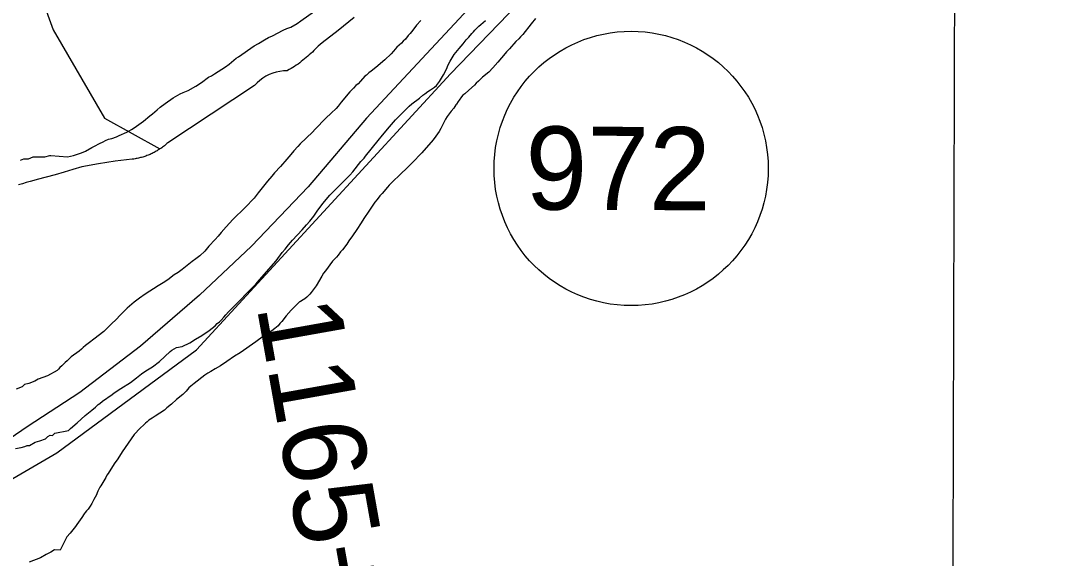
# Model space of a CAD drawing. Extents: x 3161514 to 3199414, y 831166 to 856601.
# Drawn here: x 3185519 to 3186751, y 838752 to 839399 of the extents above; entities that cross this region are included whole.
import ezdxf

# ---------------------------------------------------------------- set-up
doc = ezdxf.new("R2010")
doc.units = 0
for name, color, linetype in [('V-GRID-MAJR', 7, 'Continuous'), ('V-ROAD-CNTR', 7, 'Continuous'), ('V-ROAD-IDEN', 7, 'Continuous'), ('V-SITE-VEGE', 7, 'Continuous'), ('V-SURV-IDEN', 7, 'Continuous'), ('V-TOPO-SHOR', 7, 'Continuous')]:
    doc.layers.add(name, color=color, linetype=linetype)

msp = doc.modelspace()

# ---------------------------------------------------------------- linework, layer by layer
at = {"layer": 'V-GRID-MAJR'}
msp.add_spline([(3186635.6, 836575), (3186651.5, 842634.3), (3186667.4, 848696.7), (3186683.2, 854759.2), (3186683.2, 854762.2)], degree=3, dxfattribs=at)
at = {"layer": 'V-ROAD-CNTR'}
msp.add_lwpolyline([(3188785.6, 842348.3), (3188285.6, 841807.5), (3187778.5, 841264.8), (3187264.2, 840712), (3186692.9, 840089.5), (3186208.3, 839574.1), (3185935.3, 839281.4), (3185865.1, 839198.5), (3185797.1, 839127.5), (3185734.6, 839068.5), (3185663.3, 839007.1), (3185590.6, 838951.3), (3185527.2, 838910.2), (3185471.6, 838872.2), (3185410.6, 838843.5), (3185089.4, 838709.2), (3185045.4, 838695.8)], dxfattribs=at)
at = {"layer": 'V-ROAD-IDEN'}
msp.add_circle((3186253.9, 839220.8), 165, dxfattribs=at)
at = {"layer": 'V-SITE-VEGE'}
for p, q in [((3186065.7, 839387.2), (3186070.6, 839391.9)), ((3186070.6, 839391.9), (3186073.1, 839394.1)), ((3186073.1, 839394.1), (3186078.8, 839398.8)), ((3186133.7, 839394.7), (3186123.7, 839381.9)), ((3186138.8, 839401.1), (3186133.7, 839394.7)), ((3186055.5, 839375.5), (3186058.6, 839378.8)), ((3186058.6, 839378.8), (3186062.3, 839383.3)), ((3186062.3, 839383.3), (3186064.3, 839385.2)), ((3186064.3, 839385.2), (3186065.7, 839387.2)), ((3186120.9, 839379.2), (3186118.6, 839376.7)), ((3186123.7, 839381.9), (3186120.9, 839379.2)), ((3186040.9, 839357.7), (3186046.9, 839365.2)), ((3186046.9, 839365.2), (3186049.2, 839368)), ((3186049.2, 839368), (3186051.8, 839370.8)), ((3186051.8, 839370.8), (3186055.5, 839375.5)), ((3186107.5, 839364.7), (3186104.1, 839361.1)), ((3186115.2, 839373.3), (3186107.5, 839364.7)), ((3186118.6, 839376.7), (3186115.2, 839373.3)), ((3186036.1, 839349.9), (3186040.9, 839357.7)), ((3186097.8, 839353.9), (3186093.6, 839348.7)), ((3186100.4, 839356.7), (3186097.8, 839353.9)), ((3186104.1, 839361.1), (3186100.4, 839356.7)), ((3186028, 839333.5), (3186032, 839341)), ((3186032, 839341), (3186032.9, 839343.3)), ((3186032.9, 839343.3), (3186034.6, 839347.2)), ((3186034.6, 839347.2), (3186036.1, 839349.9)), ((3186087.6, 839341.7), (3186082.5, 839336.7)), ((3186093.6, 839348.7), (3186087.6, 839341.7)), ((3186023.4, 839325.4), (3186028, 839333.5)), ((3186075.1, 839330.4), (3186070.3, 839325.7)), ((3186082.5, 839336.7), (3186075.1, 839330.4)), ((3186009.2, 839313.3), (3186012.4, 839315.5)), ((3186012.4, 839315.5), (3186017.2, 839318.5)), ((3186017.2, 839318.5), (3186019.7, 839320.4)), ((3186019.7, 839320.4), (3186023.4, 839325.4)), ((3186065.4, 839321), (3186058.4, 839314.9)), ((3186067.4, 839323.2), (3186065.4, 839321)), ((3186070.3, 839325.7), (3186067.4, 839323.2)), ((3185990, 839298.4), (3185999.1, 839305.5)), ((3185999.1, 839305.5), (3186003.3, 839309.1)), ((3186003.3, 839309.1), (3186005.8, 839310.5)), ((3186005.8, 839310.5), (3186009.2, 839313.3)), ((3186047, 839303), (3186045.6, 839301.3)), ((3186049.6, 839307.1), (3186047, 839303)), ((3186051.5, 839309.1), (3186049.6, 839307.1)), ((3186053.8, 839310.7), (3186051.5, 839309.1)), ((3186058.4, 839314.9), (3186053.8, 839310.7)), ((3185978.6, 839287.6), (3185986.9, 839295.6)), ((3185986.9, 839295.6), (3185990, 839298.4)), ((3186040.4, 839293.2), (3186037.3, 839289.6)), ((3186043, 839297.4), (3186040.4, 839293.2)), ((3186043.8, 839298), (3186043, 839297.4)), ((3186045.6, 839301.3), (3186043.8, 839298)), ((3185963.3, 839270.7), (3185970.4, 839279.3)), ((3185970.4, 839279.3), (3185978.6, 839287.6)), ((3186030.7, 839279.9), (3186026.4, 839272.1)), ((3186032.7, 839283.2), (3186030.7, 839279.9)), ((3186037.3, 839289.6), (3186032.7, 839283.2)), ((3185954.7, 839260.9), (3185963.3, 839270.7)), ((3186025, 839269), (3186022.9, 839265.4)), ((3186026.4, 839272.1), (3186025, 839269)), ((3185934.2, 839235.4), (3185949.6, 839254.3)), ((3185949.6, 839254.3), (3185954.7, 839260.9)), ((3186015.8, 839255.4), (3186002.1, 839239.6)), ((3186018.9, 839259.6), (3186015.8, 839255.4)), ((3186020.7, 839262.4), (3186018.9, 839259.6)), ((3186022.9, 839265.4), (3186020.7, 839262.4)), ((3185918.8, 839216.8), (3185928.5, 839229)), ((3185928.5, 839229), (3185932.5, 839233.2)), ((3185932.5, 839233.2), (3185934.2, 839235.4)), ((3186002.1, 839239.6), (3185990.2, 839227.7)), ((3185915.4, 839212.6), (3185918.8, 839216.8)), ((3185986.8, 839224.1), (3185974, 839211.6)), ((3185990.2, 839227.7), (3185986.8, 839224.1)), ((3185903.2, 839200.5), (3185915.4, 839212.6)), ((3185968.6, 839206.6), (3185962.7, 839200.5)), ((3185974, 839211.6), (3185968.6, 839206.6)), ((3185891.3, 839188.8), (3185903.2, 839200.5)), ((3185960.9, 839198.3), (3185954.1, 839190.6)), ((3185962.7, 839200.5), (3185960.9, 839198.3)), ((3185882.7, 839178.6), (3185891.3, 839188.8)), ((3185945.6, 839180.3), (3185943, 839176.7)), ((3185948.1, 839183.3), (3185945.6, 839180.3)), ((3185951.6, 839187.8), (3185948.1, 839183.3)), ((3185954.1, 839190.6), (3185951.6, 839187.8)), ((3185872.1, 839163.3), (3185876.2, 839169.4)), ((3185876.2, 839169.4), (3185882.7, 839178.6)), ((3185937.3, 839168.1), (3185933, 839161.9)), ((3185943, 839176.7), (3185937.3, 839168.1)), ((3185863.3, 839153), (3185867.3, 839157.2)), ((3185867.3, 839157.2), (3185872.1, 839163.3)), ((3185929, 839155.5), (3185923.6, 839147.5)), ((3185930.4, 839157.2), (3185929, 839155.5)), ((3185933, 839161.9), (3185930.4, 839157.2)), ((3185846.3, 839134.4), (3185857.9, 839146.9)), ((3185857.9, 839146.9), (3185863.3, 839153)), ((3185923.6, 839147.5), (3185918.7, 839139.7)), ((3185841.4, 839128.9), (3185846.3, 839134.4)), ((3185914.1, 839133.8), (3185911.6, 839129.7)), ((3185918.7, 839139.7), (3185914.1, 839133.8)), ((3185826.6, 839109.7), (3185834, 839119.7)), ((3185834, 839119.7), (3185837.4, 839123.6)), ((3185837.4, 839123.6), (3185841.4, 839128.9)), ((3185904.1, 839120.5), (3185901.3, 839116.6)), ((3185906.4, 839123), (3185904.1, 839120.5)), ((3185911.6, 839129.7), (3185906.4, 839123)), ((3185806.7, 839086.7), (3185826.6, 839109.7)), ((3185894.7, 839109.4), (3185886.2, 839097.7)), ((3185897, 839111.6), (3185894.7, 839109.4)), ((3185899.3, 839114.1), (3185897, 839111.6)), ((3185901.3, 839116.6), (3185899.3, 839114.1)), ((3185883.6, 839094.7), (3185881.6, 839091.1)), ((3185886.2, 839097.7), (3185883.6, 839094.7)), ((3185790.5, 839069.8), (3185802.1, 839081.7)), ((3185802.1, 839081.7), (3185806.7, 839086.7)), ((3185881.6, 839091.1), (3185874.7, 839079.7)), ((3185784.2, 839063.1), (3185790.5, 839069.8)), ((3185867.3, 839069.7), (3185863.6, 839066.1)), ((3185869, 839071.6), (3185867.3, 839069.7)), ((3185874.7, 839079.7), (3185869, 839071.6)), ((3185774.8, 839054), (3185784.2, 839063.1)), ((3185855.1, 839060.6), (3185844.6, 839050.3)), ((3185855.4, 839060.3), (3185855.1, 839060.6)), ((3185857.4, 839061.4), (3185855.4, 839060.3)), ((3185861.4, 839064.1), (3185857.4, 839061.4)), ((3185863.6, 839066.1), (3185861.4, 839064.1)), ((3185763.7, 839041.8), (3185766, 839044.9)), ((3185766, 839044.9), (3185769.2, 839048.2)), ((3185769.2, 839048.2), (3185771.1, 839050.1)), ((3185771.1, 839050.1), (3185774.8, 839054)), ((3185844.6, 839050.3), (3185838.6, 839043.4)), ((3185753.2, 839031.6), (3185755.8, 839034.1)), ((3185755.8, 839034.1), (3185758.6, 839036.5)), ((3185758.6, 839036.5), (3185760.6, 839038.5)), ((3185760.6, 839038.5), (3185763.7, 839041.8)), ((3185831.2, 839034.2), (3185829, 839031.4)), ((3185833.5, 839036.7), (3185831.2, 839034.2)), ((3185838.6, 839043.4), (3185833.5, 839036.7)), ((3185729.8, 839015.6), (3185737.4, 839020)), ((3185737.4, 839020), (3185746.1, 839025.8)), ((3185746.1, 839025.8), (3185753.2, 839031.6)), ((3185821.6, 839025.4), (3185811.1, 839018.5)), ((3185825.3, 839028.4), (3185821.6, 839025.4)), ((3185827.3, 839029.8), (3185825.3, 839028.4)), ((3185829, 839031.4), (3185827.3, 839029.8)), ((3185713.4, 839006.5), (3185723, 839011.2)), ((3185723, 839011.2), (3185729.8, 839015.6)), ((3185802.4, 839012.1), (3185783.4, 838998.9)), ((3185805.5, 839014.6), (3185802.4, 839012.1)), ((3185811.1, 839018.5), (3185805.5, 839014.6)), ((3185686.2, 838988.7), (3185699, 839000.6)), ((3185699, 839000.6), (3185701.3, 839002.2)), ((3185701.3, 839002.2), (3185706.6, 839005.5)), ((3185706.6, 839005.5), (3185713.4, 839006.5)), ((3185776.6, 838995.1), (3185767.3, 838988.7)), ((3185783.4, 838998.9), (3185776.6, 838995.1)), ((3185677.7, 838982), (3185686.2, 838988.7)), ((3185759.9, 838983.5), (3185753.4, 838979.7)), ((3185767.3, 838988.7), (3185759.9, 838983.5)), ((3185658.8, 838968.8), (3185664.7, 838973.8)), ((3185664.7, 838973.8), (3185669.8, 838977.4)), ((3185669.8, 838977.4), (3185677.7, 838982)), ((3185741, 838972.3), (3185728, 838962.3)), ((3185744.4, 838974.5), (3185741, 838972.3)), ((3185748, 838976.7), (3185744.4, 838974.5)), ((3185753.4, 838979.7), (3185748, 838976.7)), ((3185639.8, 838956.2), (3185651.4, 838963.3)), ((3185651.4, 838963.3), (3185658.8, 838968.8)), ((3185724, 838959), (3185721.7, 838956.8)), ((3185728, 838962.3), (3185724, 838959)), ((3185617.7, 838940.7), (3185629.3, 838949)), ((3185629.3, 838949), (3185631.6, 838950.9)), ((3185631.6, 838950.9), (3185639.8, 838956.2)), ((3185714.3, 838949), (3185706.7, 838942.7)), ((3185718.3, 838952.9), (3185714.3, 838949)), ((3185721.7, 838956.8), (3185718.3, 838952.9)), ((3185604.7, 838930.2), (3185609.2, 838933.8)), ((3185609.2, 838933.8), (3185612.6, 838936.9)), ((3185612.6, 838936.9), (3185614.6, 838938.2)), ((3185614.6, 838938.2), (3185617.7, 838940.7)), ((3185700.7, 838937.4), (3185695, 838932.7)), ((3185706.7, 838942.7), (3185700.7, 838937.4)), ((3185587.1, 838914.8), (3185597, 838923.6)), ((3185597, 838923.6), (3185604.7, 838930.2)), ((3185681.2, 838922.8), (3185677.5, 838920.6)), ((3185692.5, 838930.2), (3185681.2, 838922.8)), ((3185695, 838932.7), (3185692.5, 838930.2)), ((3185579.2, 838908.1), (3185587.1, 838914.8)), ((3185663, 838908.5), (3185655.9, 838900.7)), ((3185667.3, 838912.6), (3185663, 838908.5)), ((3185669.3, 838914.3), (3185667.3, 838912.6)), ((3185671.3, 838916.2), (3185669.3, 838914.3)), ((3185673.3, 838917.9), (3185671.3, 838916.2)), ((3185677.5, 838920.6), (3185673.3, 838917.9)), ((3185549.1, 838895.7), (3185551.9, 838898.4)), ((3185551.9, 838898.4), (3185554.6, 838899.8)), ((3185554.6, 838899.8), (3185557.4, 838899.7)), ((3185557.4, 838899.7), (3185560.2, 838902.5)), ((3185560.2, 838902.5), (3185576.9, 838905.6)), ((3185576.9, 838905.6), (3185579.2, 838908.1)), ((3185655.9, 838900.7), (3185641.4, 838879.8)), ((3185513.1, 838883.8), (3185520, 838885.1)), ((3185520, 838885.1), (3185524.1, 838886.4)), ((3185524.1, 838886.4), (3185526.9, 838887.7)), ((3185526.9, 838887.7), (3185529.7, 838887.7)), ((3185529.7, 838887.7), (3185536.6, 838891.7)), ((3185536.6, 838891.7), (3185542.1, 838893)), ((3185542.1, 838893), (3185549.1, 838895.7)), ((3185636.2, 838871.5), (3185631.9, 838865.4)), ((3185641.4, 838879.8), (3185636.2, 838871.5)), ((3185631.9, 838865.4), (3185624.5, 838853.7)), ((3185621.6, 838849.2), (3185615.9, 838839.2)), ((3185623.1, 838852), (3185621.6, 838849.2)), ((3185624.5, 838853.7), (3185623.1, 838852)), ((3185614.5, 838837.3), (3185613, 838834.2)), ((3185615.9, 838839.2), (3185614.5, 838837.3)), ((3185607.3, 838822.5), (3185605, 838817.8)), ((3185610.4, 838828.4), (3185607.3, 838822.5)), ((3185611.3, 838830.6), (3185610.4, 838828.4)), ((3185611.9, 838832.5), (3185611.3, 838830.6)), ((3185613, 838834.2), (3185611.9, 838832.5)), ((3185600.4, 838811.1), (3185598.4, 838808.9)), ((3185602.9, 838814.7), (3185600.4, 838811.1)), ((3185605, 838817.8), (3185602.9, 838814.7)), ((3185592.7, 838801.1), (3185589, 838795.2)), ((3185595.5, 838805.3), (3185592.7, 838801.1)), ((3185597, 838806.9), (3185595.5, 838805.3)), ((3185598.4, 838808.9), (3185597, 838806.9)), ((3185585.2, 838790.2), (3185578.7, 838782.2)), ((3185587, 838792.7), (3185585.2, 838790.2)), ((3185589, 838795.2), (3185587, 838792.7)), ((3185574.7, 838777.8), (3185566.7, 838761.8)), ((3185578.7, 838782.2), (3185574.7, 838777.8)), ((3185559.8, 838761.9), (3185555.6, 838759.2)), ((3185566.7, 838761.8), (3185559.8, 838761.9)), ((3185543.1, 838752.5), (3185529.3, 838747.2)), ((3185550, 838756.5), (3185543.1, 838752.5)), ((3185555.6, 838759.2), (3185550, 838756.5))]:
    msp.add_line(p, q, dxfattribs=at)
for points in [[(3185765.6, 839343), (3185770.1, 839346.3), (3185778.6, 839353.5), (3185781.2, 839355.2), (3185800.4, 839368.4), (3185805.5, 839371.1), (3185812.6, 839375.5), (3185817.4, 839378.3), (3185822.2, 839380.4), (3185835.2, 839387), (3185839.7, 839389.2), (3185844.2, 839390.8), (3185852.1, 839395.2), (3185856.4, 839398.5), (3185872.8, 839409.8)], [(3186000.8, 839398.9), (3185995.7, 839393.1), (3185991.1, 839387.3), (3185988, 839383.1), (3185985.7, 839380.6), (3185982.3, 839376.2), (3185979.4, 839373.7), (3185977.5, 839371.4), (3185972.1, 839366.5), (3185967.8, 839362), (3185965, 839358.7), (3185957.6, 839351.5), (3185946.5, 839342.1), (3185941.1, 839338), (3185938.3, 839336), (3185935.5, 839333), (3185933.5, 839331.6), (3185928.1, 839325.8), (3185925.2, 839322.7), (3185922.7, 839320.5), (3185919.8, 839317.2), (3185915.3, 839312.8), (3185905, 839300.6), (3185901.3, 839295.8), (3185898.8, 839293.1), (3185893.1, 839287.3), (3185886.3, 839281.2), (3185873.5, 839268.2), (3185870.4, 839264.5), (3185855.6, 839250.4), (3185852.7, 839247.1), (3185847.9, 839241.8), (3185844.5, 839237.7), (3185839.4, 839232.1), (3185832, 839223.2), (3185824.9, 839215.5), (3185821.7, 839211.6), (3185816.3, 839205.5), (3185804.9, 839191.3), (3185800.3, 839185.2), (3185789.5, 839173.9), (3185774.5, 839159.2), (3185766.5, 839150.6), (3185760.6, 839143.9), (3185756.9, 839139.5), (3185753.2, 839135.3), (3185745.5, 839127.3), (3185740.9, 839121.5), (3185734.7, 839115.7), (3185730.1, 839112.1), (3185725.6, 839108.8), (3185713.4, 839099.4), (3185708.6, 839095.8), (3185704.1, 839092.8), (3185696.4, 839087), (3185690.8, 839083.4), (3185684.6, 839079.8), (3185669, 839069.4), (3185662.2, 839064.7), (3185656, 839060), (3185647.5, 839052.8), (3185639.8, 839045.3), (3185633.3, 839038.4), (3185629.3, 839034.8), (3185625.3, 839030.7), (3185619.4, 839024.8), (3185607.2, 839015.5), (3185602.1, 839011.3), (3185597.3, 839007.7), (3185594.4, 839005.5), (3185592.4, 839003.3), (3185589.6, 839001.1), (3185580, 838994.2), (3185575.2, 838989.5), (3185572.6, 838987.3), (3185568.9, 838983.4), (3185566.4, 838981.2), (3185564.7, 838979.5), (3185563.2, 838977.6)], [(3185518.9, 839230.9), (3185523, 839232.2), (3185528.6, 839232.2), (3185534.1, 839234.9), (3185543.7, 839234.7), (3185548.5, 839234.8), (3185554.3, 839236.2), (3185555.5, 839236.2), (3185575.5, 839234.6), (3185579.4, 839235.7), (3185582.8, 839236.5), (3185592.4, 839239.5), (3185597.4, 839241.7), (3185604.8, 839245.8), (3185607.9, 839247.7), (3185614.1, 839251), (3185618.6, 839252.9), (3185621.2, 839254.3), (3185625.1, 839255.9), (3185628.8, 839257), (3185634.4, 839258.9), (3185637.8, 839260.5), (3185647.1, 839264.6), (3185652.5, 839267.6), (3185655.9, 839269.8), (3185667.2, 839277.8), (3185674.6, 839284.1), (3185677.9, 839286.6), (3185683.6, 839291.3), (3185687.3, 839294.6), (3185693, 839299.1), (3185702.6, 839305.9), (3185711.1, 839310.6), (3185714.7, 839312.2), (3185720.9, 839314.7), (3185730, 839319.6), (3185736.8, 839324.3), (3185745.3, 839330.4), (3185748.9, 839332.3), (3185752.6, 839334.8), (3185765.6, 839343)], [(3185563.2, 838977.6), (3185551.4, 838971.5), (3185540.3, 838967.5), (3185536.2, 838964.8), (3185529.2, 838962.1), (3185523.7, 838960.8), (3185520.9, 838958.1), (3185514, 838955.4)]]:
    msp.add_lwpolyline(points, dxfattribs=at)
at = {"layer": 'V-TOPO-SHOR'}
for points in [[(3184965.2, 840839.5), (3185505.3, 839533.7), (3185558.4, 839387.7), (3185620.3, 839281.4), (3185686.8, 839244.2)], [(3185248.5, 838657.3), (3185372.5, 838768), (3185562.8, 838878.6), (3185731, 839002.6), (3186036.4, 839334.5), (3186279.9, 839586.8), (3187174, 840569.5)], [(3185920.5, 839402.3), (3185901.5, 839386.9), (3185882.2, 839371.8), (3185877.2, 839368), (3185877.2, 839368), (3185875.5, 839366.1), (3185873.8, 839364.3), (3185872.1, 839362.5), (3185870.3, 839360.8), (3185868.5, 839359), (3185866.6, 839357.3), (3185864.8, 839355.7), (3185862.9, 839354.1), (3185860.9, 839352.5), (3185859, 839350.9), (3185857, 839349.4), (3185855, 839347.9), (3185853, 839346.4), (3185850.9, 839345), (3185848.8, 839343.6), (3185846.7, 839342.3), (3185844.6, 839341), (3185842.5, 839339.7), (3185840.3, 839338.5), (3185840.1, 839338.4), (3185840.1, 839338.4), (3185835.6, 839338.2), (3185831.2, 839337.6), (3185826.8, 839336.7), (3185822.6, 839335.4), (3185818.4, 839333.7), (3185814.4, 839331.7), (3185810.6, 839329.4), (3185807, 839326.7), (3185803.7, 839323.8), (3185800.6, 839320.6), (3185800.6, 839320.6), (3185696.3, 839251.7), (3185696.3, 839251.7), (3185695.3, 839250.8), (3185694.3, 839249.9), (3185693.3, 839249), (3185692.3, 839248.2), (3185691.2, 839247.3), (3185690.1, 839246.5), (3185689, 839245.7), (3185687.9, 839244.9), (3185686.8, 839244.2), (3185685.7, 839243.4), (3185684.5, 839242.7), (3185683.4, 839242), (3185682.2, 839241.4), (3185681, 839240.7), (3185679.9, 839240.1), (3185678.7, 839239.4), (3185677.4, 839238.8), (3185676.2, 839238.3), (3185675, 839237.7), (3185673.8, 839237.2), (3185672.5, 839236.7), (3185671.2, 839236.2), (3185670, 839235.7)], [(3185670, 839235.7), (3185668.7, 839235.3), (3185667.4, 839234.9), (3185666.1, 839234.5), (3185664.8, 839234.1), (3185663.5, 839233.8), (3185662.2, 839233.4), (3185660.9, 839233.1), (3185659.6, 839232.8), (3185658.3, 839232.6), (3185656.9, 839232.3), (3185655.6, 839232.1), (3185654.3, 839231.9), (3185653.3, 839231.8), (3185653.3, 839231.8), (3185633.1, 839229.4), (3185612.9, 839226.5), (3185592.9, 839222.9), (3185592.9, 839222.9), (3185582.2, 839219.4), (3185571.6, 839216.2), (3185560.8, 839213.1), (3185550.1, 839210.2), (3185539.2, 839207.4), (3185535.1, 839206.5), (3185535.1, 839206.5), (3185530.5, 839205), (3185526, 839203.7), (3185521.4, 839202.4), (3185516.8, 839201.2)]]:
    msp.add_lwpolyline(points, dxfattribs=at)

# ---------------------------------------------------------------- texts
at = {"layer": 'V-ROAD-IDEN'}
msp.add_text('972', height=100, rotation=359.7334, dxfattribs=at).set_placement((3186126.5, 839171.4))
at = {"layer": 'V-SURV-IDEN'}
msp.add_text('1165+22.6', height=100, rotation=280.1137, dxfattribs=at).set_placement((3185803, 839055.2))

doc.saveas('drawing.dxf')
